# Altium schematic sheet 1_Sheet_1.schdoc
size 170 x 220 mm; Name: A_Customize; Symbol: A_Customize; Device: A_Customize; @Project Name: 4 channel reelyt_2026-10-30_12-22-13; REV: 1.0; Date: 2025-01-09; Sheet: 1/1; Draw By: Shobhit; Company: Your Company; Convert to PCB: yes; Add into BOM: yes; spicePre: .; @Page No: 1; @Page Count: 1; @Schematic Name: 4 channel reelyt; @Board Name: 4 channel reelyt; @Update Date: 2026-10-30; @Create Time: 06:52:15; @Update Time: 12:22:23; @Page Name: Sheet_1; @Create Date: 2026-10-30
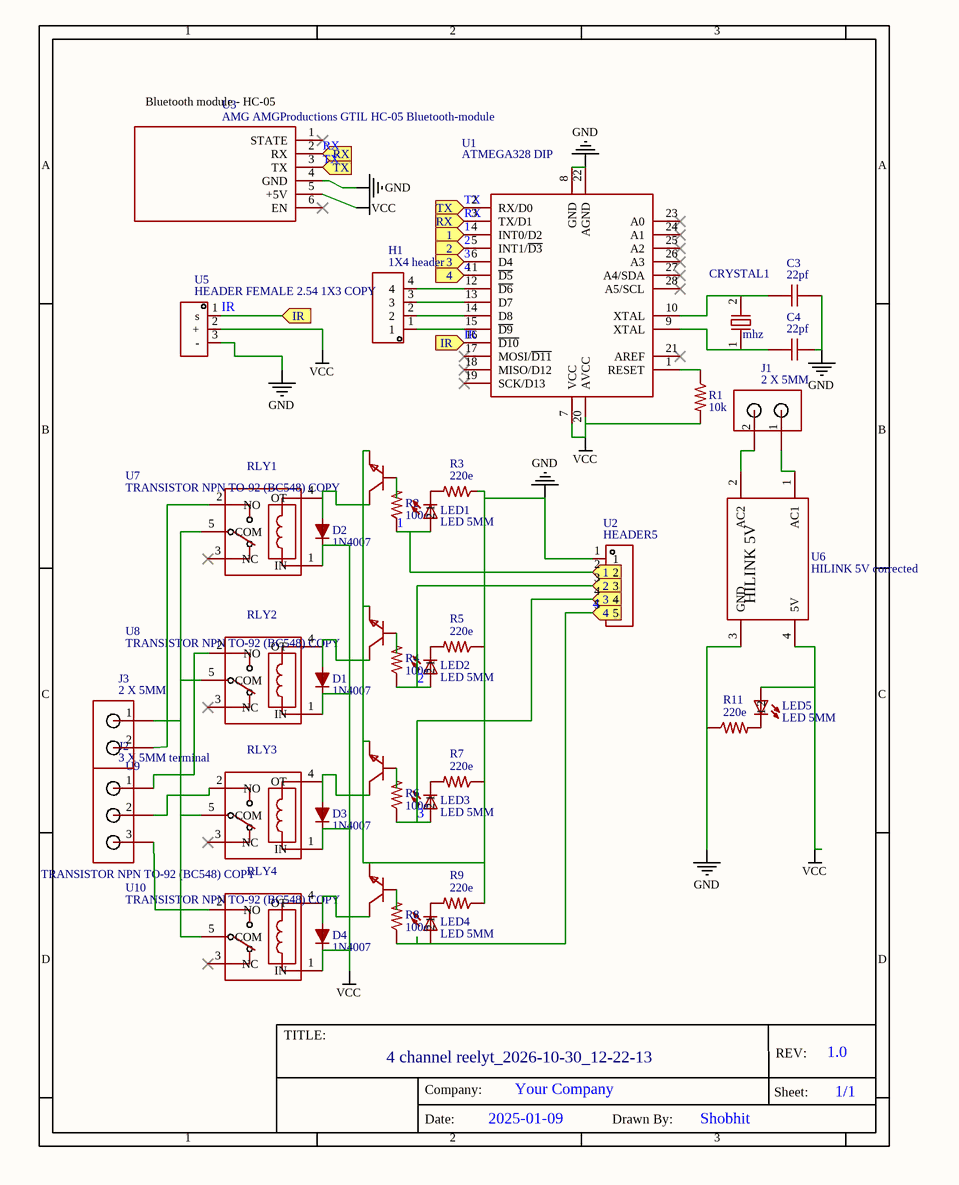
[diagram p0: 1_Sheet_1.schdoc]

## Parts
C3  22pf  [CAP-TH_L5.0-W2.5-P2.54-D0.7]
C4  22pf  [CAP-TH_L5.0-W2.5-P2.54-D0.7]
CRYSTAL1  mhz  [CRYSTAL-TH_L10.8-W4.5-P4.88]
D1  1N4007  [1N4007]
D2  1N4007  [1N4007]
D3  1N4007  [1N4007]
D4  1N4007  [1N4007]
H1  1X4 header  [HEADER - HEADER-FEMALE-2.54_1X4]
J1  2 X 5MM  [PCB MOUNT SCREW TERMINALS - 2 X 5MM]
J2  3 X 5MM terminal  [PCB MOUNT SCREW TERMINALS - 3 X 5MM]
J3  2 X 5MM  [PCB MOUNT SCREW TERMINALS - 2 X 5MM]
LED1  LED 5MM  [LED-5MM-5MM]
LED2  LED 5MM  [LED-5MM-5MM]
LED3  LED 5MM  [LED-5MM-5MM]
LED4  LED 5MM  [LED-5MM-5MM]
LED5  LED 5MM  [LED-5MM-5MM]
R1  10k  [RESISTOR-1/4W]
R2  100e  [RESISTOR-1/4W]
R3  220e  [RESISTOR-1/4W]
R4  100e  [RESISTOR-1/4W]
R5  220e  [RESISTOR-1/4W]
R6  100e  [RESISTOR-1/4W]
R7  220e  [RESISTOR-1/4W]
R8  100e  [RESISTOR-1/4W]
R9  220e  [RESISTOR-1/4W]
R11  220e  [RESISTOR-1/4W]
RLY1  Реле пылесоса 12В  [RELAY-TH_SRD-XXVDC-XL-C]  (value not drawn)
RLY2  Реле пылесоса 12В  [RELAY-TH_SRD-XXVDC-XL-C]  (value not drawn)
RLY3  Реле пылесоса 12В  [RELAY-TH_SRD-XXVDC-XL-C]  (value not drawn)
RLY4  Реле пылесоса 12В  [RELAY-TH_SRD-XXVDC-XL-C]  (value not drawn)
U1  ATMEGA328 DIP  [ATMEGA328P]
U2  HEADER5  [CONN-TH_HEADER5]
U3  AMG AMGProductions GTIL HC-05 Bluetooth-module  [WIRELESS-BLUETOOTH-HC-05]
U5  HEADER FEMALE 2.54 1X3 COPY  [HEADER - HEADER-FEMALE-2.54_1X3]
U6  HILINK 5V corrected  [FP_HILINK_5V_1A]
U7  TRANSISTOR NPN TO-92 (BC548) COPY  [TRANSISTOR NPN TO-92 (BC548)]
U8  TRANSISTOR NPN TO-92 (BC548) COPY  [TRANSISTOR NPN TO-92 (BC548)]
U9  TRANSISTOR NPN TO-92 (BC548) COPY  [TRANSISTOR NPN TO-92 (BC548)]
U10  TRANSISTOR NPN TO-92 (BC548) COPY  [TRANSISTOR NPN TO-92 (BC548)]

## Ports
1 (in), 2 (in), 3 (in), 4 (in), IR (in), RX (in), TX (in)

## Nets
GND: C3.1 C4.1 R3.1 R5.1 R7.1 R9.1 R11.1 U1.8(GND) U1.22(AGND) U2.1 U3.4(GND) U5.3(-) U6.3(GND) U7.3(E) U8.3(E) U9.3(E) U10.3(E)
VCC: D1.K D2.K D3.K D4.K LED5.1 R1.2 RLY1.1(IN) RLY2.1(IN) RLY3.1(IN) RLY4.1(IN) U1.7(VCC) U1.20(AVCC) U3.5(+5V) U5.2(+) U6.4(5V)
1: LED1.1 R2.1 U1.4(INT0/D2) U2.2 ; port 1
2: LED2.1 R4.1 U1.5(INT1/~{D3}) U2.3 ; port 2
3: LED3.1 R6.1 U1.6(D4) U2.4 ; port 3
4: LED4.1 R8.1 U1.11(~{D5}) U2.5 ; port 4
IR: U1.16(~{D10}) U5.1(s) ; port IR
RX: U1.3(TX/D1) U3.2(RX) ; port RX
TX: U1.2(RX/D0) U3.3(TX) ; port TX
NetC3_2: C3.2 CRYSTAL1.2 U1.10(XTAL)
NetC4_2: C4.2 CRYSTAL1.1 U1.9(XTAL)
NetD1_A: D1.A RLY2.4(OT) U8.1(C)
NetD2_A: D2.A RLY1.4(OT) U7.1(C)
NetD3_A: D3.A RLY3.4(OT) U9.1(C)
NetD4_A: D4.A RLY4.4(OT) U10.1(C)
NetH1_1: H1.1 U1.15(~{D9})
NetH1_2: H1.2 U1.14(D8)
NetH1_3: H1.3 U1.13(D7)
NetH1_4: H1.4 U1.12(~{D6})
NetJ1_1: J1.1 U6.1(AC1)
NetJ1_2: J1.2 U6.2(AC2)
NetJ2_1: J2.1 RLY2.2(NO)
NetJ2_2: J2.2 RLY3.2(NO)
NetJ2_3: J2.3 RLY4.2(NO)
NetJ3_1: J3.1 RLY1.5(COM) RLY2.5(COM) RLY3.5(COM) RLY4.5(COM)
NetJ3_2: J3.2 RLY1.2(NO)
NetLED1_2: LED1.2 R3.2
NetLED2_2: LED2.2 R5.2
NetLED3_2: LED3.2 R7.2
NetLED4_2: LED4.2 R9.2
NetLED5_2: LED5.2 R11.2
NetR1_1: R1.1 U1.1(RESET)
NetR2_2: R2.2 U7.2(B)
NetR4_2: R4.2 U8.2(B)
NetR6_2: R6.2 U9.2(B)
NetR8_2: R8.2 U10.2(B)

Not connected (* = marked no-connect by the designer): RLY1 3(NC)*; RLY2 3(NC)*; RLY3 3(NC)*; RLY4 3(NC)*; U1 17(MOSI/~{D11})* 18(MISO/D12)* 19(SCK/D13)* 21(AREF)* 23(A0)* 24(A1)* 25(A2)* 26(A3)* 27(A4/SDA)* 28(A5/SCL)*; U3 1(STATE)* 6(EN)*

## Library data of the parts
C3 C4 = 22pf: Manufacturer: Dersonic(德尔创); Manufacturer Part: CC1H103ZA1AD3F4D10MF; Convert to PCB: yes; nameAlias: Value; Contributor: LCSC
CRYSTAL1 = mhz: Manufacturer: HUAXIN(华昕); Manufacturer Part: SP2005M52920001; Convert to PCB: yes; nameAlias: Value; Contributor: lcsc
D1-D4 = 1N4007: Convert to PCB: yes; Contributor: Ryan Baga
H1 = 1X4 header: Convert to PCB: yes; Contributor: sohail.hdesign
J1 J3 = 2 X 5MM: Convert to PCB: yes; Contributor: rnor
J2 = 3 X 5MM terminal: Convert to PCB: yes; Contributor: Ap9639
LED1-LED5 = LED 5MM: Convert to PCB: yes; Contributor: justin123574
R1 = 10k: Convert to PCB: yes; Contributor: Essam12 M
R2 R4 R6 R8 = 100e: Convert to PCB: yes; Contributor: Essam12 M
R3 R5 R7 R9 R11 = 220e: Convert to PCB: yes; Contributor: Essam12 M
RLY1-RLY4 = Реле пылесоса 12В: Manufacturer: 松乐; Manufacturer Part: SRD-24VDC-SL-C; Value: Relay; Convert to PCB: yes; Contributor: Павел Майоров
U1 = ATMEGA328 DIP: Convert to PCB: yes; Contributor: electromaniax
U2 = HEADER5: Manufacturer: null; Convert to PCB: yes; Contributor: LCSC
U3 = AMG AMGProductions GTIL HC-05 Bluetooth-module: Convert to PCB: yes
U5 = HEADER FEMALE 2.54 1X3 COPY: Convert to PCB: yes; Contributor: nixoncali614
U6 = HILINK 5V corrected: Convert to PCB: yes; Contributor: RaspAutomacao
U7-U10 = TRANSISTOR NPN TO-92 (BC548) COPY: Convert to PCB: yes; Contributor: angelkastro234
